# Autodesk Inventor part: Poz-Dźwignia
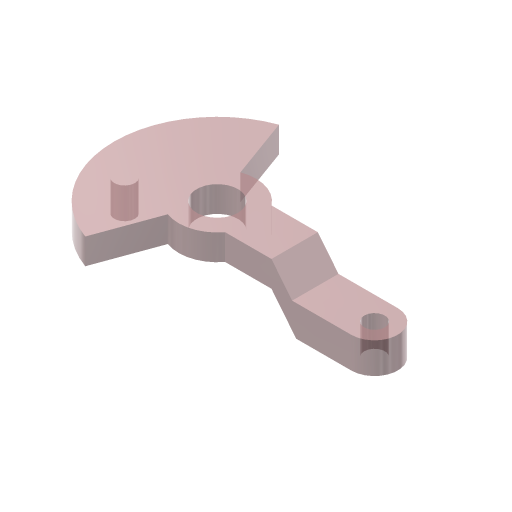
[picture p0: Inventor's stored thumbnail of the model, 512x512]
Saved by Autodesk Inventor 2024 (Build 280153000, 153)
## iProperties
Company: ATC
Shininess: 20.0
Angle Display Precision: 2
Document Length Units: 11269
Document Angle Units: 11279
Document Time Units: 11290
Document Mass Units: 11283
Document Length Units Precision: 3
Document Angle Units Precision: 2
Created: 2023-03
Part Number: Poz-Dźwignia
Material: Standardowy
Document SubType Name: Modelowanie
Designer: Andrzej Jaskulski
Density: 1 g/cm^3
Appearance: Jasnoczerwone
Checked By: A.J.
Engr Approved By: Andrzej Jaskulski
Mfg Approved By: Andrzej Jaskulski
Authority: A.J.
Density: 0.0
Volumn: 0.0
Area: 0.0
PropertySet Name: Model Information
Control State: 0
Master: False
Checked Out: False
Title: A.J.: Kurs R2024-MEP
Author: Andrzej Jaskulski
Revision Number: 1/24
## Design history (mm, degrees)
node "Bryła1"
node "Korpusy bryłowe"
node "Korpusy powierzchniowe"
node "Początek"
sketch "Szkic1"
  geometry: L1 (36.371, 18.985)-(54.371, 18.985); L2 (36.371, 0.985)-(54.371, 0.985); L3 (19.241, -4.11)-(10.691, -27.603); L4 (19.241, 24.081)-(10.691, 47.573); L5 (-41.915, 9.985)-(91.63, 9.985); L6 (54.371, 0.985)-(54.371, 18.985); L7 (19.241, -4.11)-(24.371, 9.985); L8 (19.241, 24.081)-(24.371, 9.985); C1 r 8 at (24.371, 9.985); C2 r 4 at (-11.629, 9.985); A1 r 15 centre (24.371, 9.985) between (19.241, 24.081) and (19.241, -4.11); A2 r 40 centre (24.371, 9.985) between (10.691, 47.573) and (10.691, -27.603)
  constraints: 16 end point, 6 point on circle, 4 centre point, 2 collinear, 2 point on line, 1 coincident, 1 concentric, 1 horizontal, 1 parallel, 1 perpendicular, 1 tangent, 3 other
  dimensions: "d4" = 40 radius of A2; "d5" = 30 diameter of A1; "d6" = 16 diameter of C1; "d7" = 8 diameter of C2; "d22" = 140 deg angle of L3 L4; "d23" = 30 distance from line of L6 C1.centre; "d24" = 18 distance of L2.end L1.end
extrude "Wyciągnięcie proste1" new body sketch "Szkic1" distance "d2" = 10; taper "d3" = 0 deg
extrude "Wyciągnięcie proste2" join sketch "Szkic1" distance "d8" = 12; taper "d9" = 0 deg
extrude "Wyciągnięcie proste3" cut sketch "Szkic1" extent not by distance; stored distance "d12" = 12; taper "d13" = 0 deg
node "Oś konstrukcyjna1"
node "Płaszczyzna konstrukcyjna2"
sketch "Szkic5"
  geometry: L1 (30, 0)-(30, 10) reference; L2 (30, 10)-(38, 0); L3 (38, 0)-(70, 0); L4 (70, 0)-(70, -12); L5 (70, -12)-(39.6, -12); L6 (39.6, -12)-(30, 0); L7 (0, -16.4)-(0, 14.4) reference
  constraints: 10 end point, 3 perpendicular, 1 parallel, 1 point on line
  dimensions: "d19" = 12 distance between parallel lines of L3 L5; "d20" = 38 distance from line of L2.end L7; "d28" = 70 distance between parallel lines of L4 L7
extrude "Wyciągnięcie proste5" join sketch "Szkic5" stored distance "d25" = 17.57962; taper "d26" = 0 deg
fillet "Zaokrąglenie1" dims "d27" = 9
sketch "Szkic6"
  geometry: A1 r 9 centre (23, 9) between (23, 0) and (23, 18) reference; 1 further point
hole "Otwór1" sketch "Szkic6" diameter "d30" = 8; stored, may be unused: countersink angle "d34" = 82 deg, drill point angle "d36" = 118 deg; dims "d31" = 6, "d32" = 4, "d33" = 2, "d35" = 8
node "Płaszczyzna YZ"
node "Płaszczyzna XZ"
node "Płaszczyzna XY"
node "Oś X"
node "Oś Y"
node "Oś Z"
node "Punkt środkowy"
other parameters: "d0" = 110 deg, "d18" = 0
